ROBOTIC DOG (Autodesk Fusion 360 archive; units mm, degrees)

design "WAVEGO PRO BETA" references "SCS215", "支架"
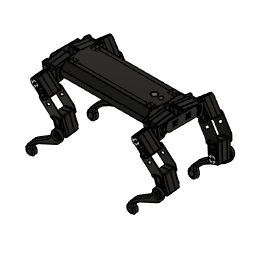
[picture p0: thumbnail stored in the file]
parameter "d7" = 1.5
parameter "d13" = 1.5
parameter "d21" = 2.5
parameter "d70" = 1.5
sketch "草图2" plane through (-2804.9918, -1775.266, 0) normal (0, 0, 1) x axis (1, 0, 0)
  line L1 (3425.3355, 1308.4769) -> (3426.7345, 1308.3163)
  line L2 (3447.7144, 1337.2156) -> (3447.3133, 1335.8658)
  line L3 (3434.7333, 1332.7657) -> (3435.8804, 1331.9489)
  line L4 (3453.3078, 1578.136) -> (3453.6616, 1576.7729)
  line L5 (3424.9361, 1311.1179) -> (3426.217, 1311.703)
  line L6 (3428.9646, 1326.8646) -> (3430.3219, 1326.4895)
  line L7 (3458.8158, 1577.0653) -> (3457.9772, 1575.934)
  line L8 (3439.6409, 1335.486) -> (3439.7256, 1334.0804)
  line L9 (3432.6458, 1331.0994) -> (3433.2062, 1329.8075)
  line L10 (3427.1623, 1303.1715) -> (3428.1658, 1304.1594)
  line L11 (3471.8291, 1318.4375) -> (3470.4301, 1318.5981)
  line L12 (3433.9754, 1294.6993) -> (3435.1504, 1295.4755)
  line L13 (3472.1305, 1310.1862) -> (3470.8708, 1310.8157)
  line L14 (3442.1724, 1336.3379) -> (3442.971, 1335.178)
  line L15 (3449.4501, 1289.6987) -> (3449.8513, 1291.0486)
  line L16 (3431.972, 1296.4657) -> (3432.5771, 1297.7373)
  line L17 (3470.0023, 1323.7429) -> (3468.9988, 1322.755)
  line L18 (3464.5187, 1295.815) -> (3463.9583, 1297.1069)
  line L19 (3425.034, 1316.7281) -> (3426.2937, 1316.0987)
  line L20 (3438.7851, 1291.8094) -> (3438.9188, 1293.2112)
  line L21 (3428.4408, 1300.8264) -> (3429.8103, 1301.1539)
  line L22 (3425.5621, 1319.3464) -> (3426.9658, 1319.4581)
  line L23 (3427.5729, 1324.5848) -> (3428.5414, 1323.5625)
  line L24 (3454.9922, 1290.5765) -> (3454.1935, 1291.7363)
  line L25 (3446.7799, 1289.764) -> (3446.4262, 1291.1271)
  line L26 (3471.6025, 1307.568) -> (3470.1987, 1307.4562)
  line L27 (3455.8926, 1336.0797) -> (3455.054, 1334.9484)
  line L28 (3450.3846, 1337.1503) -> (3450.7384, 1335.7873)
  line L29 (3458.3794, 1335.105) -> (3458.2457, 1333.7032)
  line L30 (3462.4313, 1294.1487) -> (3461.2841, 1294.9654)
  line L31 (3468.7238, 1326.088) -> (3467.3542, 1325.7605)
  line L32 (3463.1891, 1332.2151) -> (3462.0141, 1331.4389)
  line L33 (3441.2719, 1290.8347) -> (3442.1105, 1291.966)
  line L34 (3472.2284, 1315.7965) -> (3470.9475, 1315.2114)
  line L35 (3468.2, 1300.0497) -> (3466.8426, 1300.4249)
  line L36 (3457.5237, 1291.4283) -> (3457.4389, 1292.834)
  line L37 (3437.6565, 1573.7513) -> (3438.8036, 1572.9346)
  line L38 (3465.1926, 1330.4486) -> (3464.5875, 1329.1771)
  line L39 (3445.0956, 1577.3235) -> (3445.8942, 1576.1637)
  line L40 (3469.5916, 1302.3295) -> (3468.6232, 1303.3518)
  line L41 (3431.8878, 1567.8503) -> (3433.2451, 1567.4751)
  line L42 (3427.8593, 1552.1035) -> (3429.1402, 1552.6886)
  line L43 (3431.364, 1541.812) -> (3432.7335, 1542.1396)
  line L44 (3442.5641, 1576.4717) -> (3442.6488, 1575.066)
  line L45 (3428.4853, 1560.3321) -> (3429.889, 1560.4438)
  line L46 (3430.4961, 1565.5705) -> (3431.4646, 1564.5482)
  line L47 (3457.9153, 1531.5621) -> (3457.1167, 1532.722)
  line L48 (3428.2586, 1549.4625) -> (3429.6577, 1549.3019)
  line L49 (3450.6376, 1578.2013) -> (3450.2365, 1576.8514)
  line L50 (3465.3544, 1535.1343) -> (3464.2073, 1535.9511)
  line L51 (3452.3733, 1530.6844) -> (3452.7744, 1532.0342)
  line L52 (3436.8986, 1535.6849) -> (3438.0736, 1536.4612)
  line L53 (3441.7083, 1532.795) -> (3441.842, 1534.1968)
  line L54 (3444.1951, 1531.8203) -> (3445.0337, 1532.9516)
  line L55 (3434.8951, 1537.4514) -> (3435.5003, 1538.7229)
  line L56 (3460.4469, 1532.414) -> (3460.3621, 1533.8196)
  line L57 (3435.569, 1572.085) -> (3436.1294, 1570.7931)
  line L58 (3467.4419, 1536.8006) -> (3466.8815, 1538.0925)
  line L59 (3472.5148, 1543.3152) -> (3471.5464, 1544.3375)
  line L60 (3449.7031, 1530.7497) -> (3449.3494, 1532.1127)
  line L61 (3474.7523, 1559.4231) -> (3473.3533, 1559.5837)
  line L62 (3466.1123, 1573.2007) -> (3464.9373, 1572.4245)
  line L63 (3475.0537, 1551.1719) -> (3473.794, 1551.8013)
  line L64 (3430.0854, 1544.1571) -> (3431.089, 1545.145)
  line L65 (3475.1516, 1556.7821) -> (3473.8707, 1556.197)
  line L66 (3461.3026, 1576.0906) -> (3461.1689, 1574.6888)
  line L67 (3471.647, 1567.0736) -> (3470.2774, 1566.7461)
  line L68 (3472.9255, 1564.7285) -> (3471.9219, 1563.7406)
  line L69 (3427.9572, 1557.7138) -> (3429.2169, 1557.0843)
  line L70 (3468.1158, 1571.4343) -> (3467.5106, 1570.1627)
  line L71 (3471.1231, 1541.0354) -> (3469.7658, 1541.4105)
  line L72 (3474.5257, 1548.5536) -> (3473.1219, 1548.4419)
  line L73 (2864.3592, 1577.4683) -> (2882.3592, 1577.4683)
  line L74 (2855.3592, 1575.9683) -> (2855.3592, 1366.9683)
  line L75 (2882.3592, 1365.4683) -> (2864.3592, 1365.4683)
  line L76 (2882.3592, 1577.4683) -> (2894.3592, 1577.4683)
  line L77 (3684.4233, 1482.2767) -> (3273.5094, 1482.2767)
  line L78 (2868.1341, 1241.7898) -> (2902.3889, 1241.7898)
  line L79 (3450.2053, 1418.8111) -> (3444.2053, 1422.2752)
  line L80 (2863.9041, 1245.3984) -> (2867.0734, 1242.2291)
  line L81 (2923.389, 1259.793) -> (2922.229, 1264.1224)
  line L82 (2869.3498, 1247.3975) -> (2869.3498, 1249.0398)
  line L83 (3684.4233, 1603.763) -> (3684.4233, 1257.736)
  line L84 (3793.7104, 1574.3581) -> (3792.0673, 1572.7149)
  line L85 (2882.3592, 1365.4683) -> (2894.3592, 1365.4683)
  line L86 (3450.3053, 1432.8407) -> (3456.3053, 1429.3766)
  line L87 (2908.4677, 1244.64) -> (2908.645, 1244.5376)
  line L88 (2881.7917, 1250.6398) -> (2884.7917, 1250.6398)
  line L89 (2868.1341, 1271.4898) -> (2910.347, 1271.4898)
  line L90 (3456.3553, 1429.29) -> (3456.3553, 1422.3618)
  line L91 (2874.2917, 1263.4398) -> (2874.2917, 1249.8398)
  line L92 (3798.8404, 1565.9418) -> (3797.2732, 1567.509)
  line L93 (2880.2917, 1261.1398) -> (2880.2917, 1252.1398)
  line L94 (3450.3053, 1418.8111) -> (3456.3053, 1422.2752)
  line L95 (3450.2053, 1432.8407) -> (3444.2053, 1429.3766)
  line L96 (2908.4311, 1244.7766) -> (2909.2522, 1246.1988)
  line L97 (2886.2917, 1261.1398) -> (2886.2917, 1252.1398)
  line L98 (3811.2797, 1573.9877) -> (3824.0077, 1565.9598)
  line L99 (3684.4233, 1375.9852) -> (3273.5094, 1375.9852)
  line L100 (2894.3592, 1365.4683) -> (2912.3592, 1365.4683)
  line L101 (3444.1553, 1429.29) -> (3444.1553, 1422.3618)
  line L102 (2869.2498, 1265.9821) -> (2869.0451, 1265.9821)
  line L103 (2910.1433, 1243.6725) -> (2912.1438, 1242.5176)
  line L104 (3990.4322, 1603.763) -> (3729.1891, 1603.763)
  line L105 (2919.4856, 1259.8538) -> (2921.4861, 1258.6989)
  line L106 (2906.6801, 1239.3123) -> (2902.3889, 1241.7898)
  line L107 (2513.8475, 1418.2797) -> (2465.8475, 1418.2797)
  line L108 (2909.0692, 1246.8818) -> (2905.4822, 1248.9528)
  line L109 (2863.9041, 1267.8811) -> (2867.0734, 1271.0504)
  line L110 (2881.7917, 1262.6398) -> (2884.7917, 1262.6398)
  line L111 (2867.3149, 1247.2975) -> (2865.005, 1247.2975)
  line L112 (2912.1477, 1240.3225) -> (2907.8183, 1239.1624)
  line L113 (2905.3724, 1249.3626) -> (2912.1724, 1261.1405)
  line L114 (3729.1891, 1488.7955) -> (3990.4322, 1488.7955)
  line L115 (2869.3498, 1265.8821) -> (2869.3498, 1264.2398)
  line L116 (2869.2498, 1247.2975) -> (2869.0451, 1247.2975)
  line L117 (3729.1891, 1603.763) -> (3729.1891, 1488.7955)
  line L118 (2921.5301, 1265.0332) -> (2910.347, 1271.4898)
  line L119 (2867.3149, 1265.9821) -> (2865.005, 1265.9821)
  line L120 (2869.8498, 1249.5398) -> (2873.9917, 1249.5398)
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extrude "拉伸1" new body sketch "草图2" along normal blind 2
copy_paste "复制和粘贴1"
extrude "拉伸1" new body sketch "草图2" along normal blind 2
copy_paste "复制和粘贴2"
copy_paste "复制和粘贴3"
copy_paste "复制和粘贴4"
extrude "拉伸1" new body sketch "草图2" along normal blind 1.5
step "转换为钣金1"
step "折弯1" BendAngle 90 BendAngle 90 BendAngle 90 BendAngle 90 BendRadius 0.01
copy_paste "复制和粘贴5"
extrude "拉伸1" new body sketch "草图2" along normal blind 1.5
step "转换为钣金1"
step "折弯1" BendAngle 45 BendAngle 45 BendAngle 45 BendAngle 45 BendRadius 0.01
copy_paste "复制和粘贴6"
extrude "拉伸1" new body sketch "草图2" along normal blind 1.5
copy_paste "复制和粘贴7"
copy_paste "复制和粘贴8"
copy_paste "复制和粘贴9"
copy_paste "复制和粘贴10"
copy_paste "复制和粘贴11"
copy_paste "复制和粘贴12"
copy_paste "复制和粘贴13"
extrude "拉伸1" new body sketch "草图2" along normal blind 1.5
position "位置1"
position "位置2"
ground "地面"
joint "装配1" alignAngle 180 alignOffsetX 0 alignOffsetY 0 alignOffsetZ 0
joint "装配4" alignAngle 0 alignOffsetX 0 alignOffsetY 0 alignOffsetZ 0
joint "装配5" alignAngle 180 alignOffsetX 0 alignOffsetY 0 alignOffsetZ 0
move_face "MoveFace1"
move_face "MoveFace2"
move_face "MoveFace3"
move_face "MoveFace4"
move_face "MoveFace5"
joint "装配6" alignAngle 180 alignOffsetX 0 alignOffsetY 0 alignOffsetZ 0
component_insert "插入零部件1"
joint "装配7" alignAngle 0 alignOffsetX 0 alignOffsetY 0 alignOffsetZ 0
position "位置3"
component_insert "插入零部件2"
joint "装配8" alignAngle 180 alignOffsetX 0 alignOffsetY 0 alignOffsetZ 0
component_insert "插入零部件3"
component_insert "插入零部件4"
joint "装配9" alignAngle 180 alignOffsetX 0 alignOffsetY 0 alignOffsetZ 0
joint "装配10" alignAngle 0 alignOffsetX 0 alignOffsetY 0 alignOffsetZ 0
sketch "草图3" plane through (-2362.4388, -1816.6745, 0) normal (0, 0, 1) x axis (1, 0, 0)
  line L1 (2599.7507, 1404.8271) -> (2599.7507, 1406.4694)
  line L2 (2597.7158, 1423.4116) -> (2595.4059, 1423.4116)
  line L3 (2599.7507, 1423.3116) -> (2599.7507, 1421.6694)
  line L4 (2604.6926, 1420.8694) -> (2604.6926, 1407.2694)
  line L5 (2594.305, 1425.3107) -> (2597.4743, 1428.48)
  line L6 (2610.6926, 1428.9194) -> (2610.6926, 1399.2194)
  line L7 (2599.6507, 1423.4116) -> (2599.446, 1423.4116)
  line L8 (2598.535, 1399.2194) -> (2610.6926, 1399.2194)
  line L9 (2597.7158, 1404.7271) -> (2595.4059, 1404.7271)
  line L10 (2654.2345, 1404.7271) -> (2654.4393, 1404.7271)
  line L11 (2654.1345, 1404.8271) -> (2654.1345, 1406.4694)
  line L12 (2600.2507, 1421.1694) -> (2604.3926, 1421.1694)
  line L13 (2600.2507, 1406.9694) -> (2604.3926, 1406.9694)
  line L14 (2612.0926, 1428.9194) -> (2610.6926, 1428.9194)
  line L15 (2620.8122, 1460.1634) -> (2605.4335, 1460.1634)
  line L16 (2654.1345, 1423.3116) -> (2654.1345, 1421.6694)
  line L17 (2656.4335, 1676.1634) -> (2641.0549, 1676.1634)
  line L18 (2659.5803, 1402.828) -> (2656.411, 1399.6587)
  line L19 (2656.1694, 1404.7271) -> (2658.4793, 1404.7271)
  line L20 (2638.1926, 1402.8194) -> (2641.7926, 1399.2194)
  line L21 (2615.6926, 1402.8194) -> (2612.0926, 1399.2194)
  line L22 (2598.535, 1428.9194) -> (2610.6926, 1428.9194)
  line L23 (2599.6507, 1404.7271) -> (2599.446, 1404.7271)
  line L24 (2638.1926, 1402.8194) -> (2615.6926, 1402.8194)
  line L25 (2603.9335, 1674.6634) -> (2603.9335, 1461.6634)
  line L26 (2620.8122, 1676.1634) -> (2605.4335, 1676.1634)
  line L27 (2641.7926, 1428.9194) -> (2643.1926, 1428.9194)
  line L28 (2643.1926, 1428.9194) -> (2643.1926, 1399.2194)
  line L29 (2594.305, 1402.828) -> (2597.4743, 1399.6587)
  line L30 (2656.4335, 1460.1634) -> (2641.0549, 1460.1634)
  line L31 (2653.6345, 1421.1694) -> (2649.4926, 1421.1694)
  line L32 (2655.3503, 1399.2194) -> (2643.1926, 1399.2194)
  line L33 (2615.6926, 1425.3194) -> (2612.0926, 1428.9194)
  line L34 (2659.5803, 1425.3107) -> (2656.411, 1428.48)
  line L35 (2653.6345, 1406.9694) -> (2649.4926, 1406.9694)
  line L36 (2657.9335, 1461.6634) -> (2657.9335, 1674.6634)
  line L37 (2639.9942, 1459.7241) -> (2639.3729, 1459.1027)
  line L38 (2622.4942, 1459.1027) -> (2621.8729, 1459.7241)
  line L39 (2622.4942, 1677.2241) -> (2621.8729, 1676.6027)
  line L40 (2612.0926, 1399.2194) -> (2610.6926, 1399.2194)
  line L41 (2649.1926, 1420.8694) -> (2649.1926, 1407.2694)
  line L42 (2638.1926, 1425.3194) -> (2615.6926, 1425.3194)
  line L43 (2654.2345, 1423.4116) -> (2654.4393, 1423.4116)
  line L44 (2638.3122, 1677.6634) -> (2623.5549, 1677.6634)
  line L45 (2639.9942, 1676.6027) -> (2639.3729, 1677.2241)
  line L46 (2655.3503, 1428.9194) -> (2643.1926, 1428.9194)
  line L47 (2656.1694, 1423.4116) -> (2658.4793, 1423.4116)
  line L48 (2638.1926, 1425.3194) -> (2641.7926, 1428.9194)
  line L49 (2638.3122, 1458.6634) -> (2623.5549, 1458.6634)
  line L50 (2641.7926, 1399.2194) -> (2643.1926, 1399.2194)
  arc A1 centre (2598.5809, 1403.8194) radius 1 clockwise from (2599.3332, 1404.4782) to (2597.8287, 1404.4782)
  arc A2 centre (2595.0121, 1424.6036) radius 1 clockwise from (2594.2244, 1423.9875) to (2594.305, 1425.3107)
  arc A3 centre (2595.0121, 1403.5351) radius 1 clockwise from (2594.305, 1402.828) to (2594.2244, 1404.1512)
  arc A4 centre (2598.535, 1427.4194) radius 1.5 clockwise from (2597.4743, 1428.48) to (2598.535, 1428.9194)
  circle C1 centre (2602.3309, 1424.3194) radius 1
  arc A5 centre (2595.4059, 1403.2271) radius 1.5 clockwise from (2594.2244, 1404.1512) to (2595.4059, 1404.7271)
  arc A6 centre (2599.446, 1404.5771) radius 0.15 clockwise from (2599.3332, 1404.4782) to (2599.446, 1404.7271)
  arc A7 centre (2600.2507, 1406.4694) radius 0.5 clockwise from (2599.7507, 1406.4694) to (2600.2507, 1406.9694)
  arc A8 centre (2656.1694, 1404.5771) radius 0.15 clockwise from (2656.0566, 1404.4782) to (2656.1694, 1404.7271)
  arc A9 centre (2597.7158, 1404.5771) radius 0.15 clockwise from (2597.7158, 1404.7271) to (2597.8287, 1404.4782)
  arc A10 centre (2598.5809, 1424.3194) radius 1 clockwise from (2597.8287, 1423.6605) to (2599.3332, 1423.6605)
  arc A11 centre (2654.4393, 1404.5771) radius 0.15 clockwise from (2654.4393, 1404.7271) to (2654.5521, 1404.4782)
  arc A12 centre (2655.3043, 1403.8194) radius 1 clockwise from (2656.0566, 1404.4782) to (2654.5521, 1404.4782)
  circle C2 centre (2651.5543, 1403.8194) radius 1
  arc A13 centre (2653.6345, 1406.4694) radius 0.5 clockwise from (2653.6345, 1406.9694) to (2654.1345, 1406.4694)
  arc A14 centre (2598.535, 1400.7194) radius 1.5 clockwise from (2598.535, 1399.2194) to (2597.4743, 1399.6587)
  arc A15 centre (2599.6507, 1404.8271) radius 0.1 clockwise from (2599.7507, 1404.8271) to (2599.6507, 1404.7271)
  arc A16 centre (2597.7158, 1423.5616) radius 0.15 clockwise from (2597.8287, 1423.6605) to (2597.7158, 1423.4116)
  arc A17 centre (2631.8658, 1417.0593) radius 0.36 clockwise from (2631.5581, 1416.8724) to (2631.8707, 1417.4193)
  arc A18 centre (2604.3926, 1407.2694) radius 0.3 clockwise from (2604.6926, 1407.2694) to (2604.3926, 1406.9694)
  arc A19 centre (2605.4335, 1461.6634) radius 1.5 clockwise from (2605.4335, 1460.1634) to (2603.9335, 1461.6634)
  arc A20 centre (2620.8122, 1677.6634) radius 1.5 clockwise from (2621.8729, 1676.6027) to (2620.8122, 1676.1634)
  arc A21 centre (2629.9326, 1409.1462) radius 0.36 clockwise from (2629.7457, 1409.4539) to (2630.2925, 1409.1413)
  arc A22 centre (2649.4926, 1420.8694) radius 0.3 clockwise from (2649.1926, 1420.8694) to (2649.4926, 1421.1694)
  arc A23 centre (2626.9426, 1414.0694) radius 5.4 clockwise from (2629.7457, 1409.4539) to (2624.1396, 1409.4539)
  arc A24 centre (2600.2507, 1421.6694) radius 0.5 clockwise from (2600.2507, 1421.1694) to (2599.7507, 1421.6694)
  arc A25 centre (2655.3503, 1400.7194) radius 1.5 clockwise from (2656.411, 1399.6587) to (2655.3503, 1399.2194)
  arc A26 centre (2604.3926, 1420.8694) radius 0.3 clockwise from (2604.3926, 1421.1694) to (2604.6926, 1420.8694)
  arc A27 centre (2595.4059, 1424.9116) radius 1.5 clockwise from (2595.4059, 1423.4116) to (2594.2244, 1423.9875)
  circle C3 centre (2602.3309, 1403.8194) radius 1
  arc A28 centre (2654.4393, 1423.5616) radius 0.15 clockwise from (2654.5521, 1423.6605) to (2654.4393, 1423.4116)
  arc A29 centre (2629.9326, 1418.9926) radius 0.36 clockwise from (2630.2925, 1418.9974) to (2629.7457, 1418.6849)
  arc A30 centre (2641.0549, 1458.6634) radius 1.5 clockwise from (2639.9942, 1459.7241) to (2641.0549, 1460.1634)
  arc A31 centre (2654.2345, 1404.8271) radius 0.1 clockwise from (2654.2345, 1404.7271) to (2654.1345, 1404.8271)
  arc A32 centre (2622.0194, 1417.0593) radius 0.36 clockwise from (2622.0146, 1417.4193) to (2622.3271, 1416.8724)
  arc A33 centre (2656.1694, 1423.5616) radius 0.15 clockwise from (2656.1694, 1423.4116) to (2656.0566, 1423.6605)
  arc A34 centre (2626.9426, 1414.0694) radius 5.4 clockwise from (2631.5581, 1416.8724) to (2631.5581, 1411.2663)
  arc A35 centre (2655.3503, 1427.4194) radius 1.5 clockwise from (2655.3503, 1428.9194) to (2656.411, 1428.48)
  arc A36 centre (2599.446, 1423.5616) radius 0.15 clockwise from (2599.446, 1423.4116) to (2599.3332, 1423.6605)
  arc A37 centre (2599.6507, 1423.3116) radius 0.1 clockwise from (2599.6507, 1423.4116) to (2599.7507, 1423.3116)
  arc A38 centre (2653.6345, 1421.6694) radius 0.5 clockwise from (2654.1345, 1421.6694) to (2653.6345, 1421.1694)
  arc A39 centre (2622.0194, 1411.0794) radius 0.36 clockwise from (2622.3271, 1411.2663) to (2622.0146, 1410.7195)
  circle C4 centre (2653.4335, 1669.1634) radius 1.3
  arc A40 centre (2658.4793, 1424.9116) radius 1.5 clockwise from (2659.6608, 1423.9875) to (2658.4793, 1423.4116)
  arc A41 centre (2658.8732, 1424.6036) radius 1 clockwise from (2659.5803, 1425.3107) to (2659.6608, 1423.9875)
  arc A42 centre (2658.4793, 1403.2271) radius 1.5 clockwise from (2658.4793, 1404.7271) to (2659.6608, 1404.1512)
  circle C5 centre (2608.4335, 1477.1634) radius 1.3
  arc A43 centre (2656.4335, 1674.6634) radius 1.5 clockwise from (2656.4335, 1676.1634) to (2657.9335, 1674.6634)
  circle C6 centre (2651.5543, 1424.3194) radius 1
  circle C7 centre (2608.4335, 1659.1634) radius 1.3
  circle C8 centre (2630.9335, 1662.1634) radius 4
  arc A44 centre (2631.8658, 1411.0794) radius 0.36 clockwise from (2631.8707, 1410.7195) to (2631.5581, 1411.2663)
  arc A45 centre (2638.3122, 1676.1634) radius 1.5 clockwise from (2638.3122, 1677.6634) to (2639.3729, 1677.2241)
  arc A46 centre (2658.8732, 1403.5351) radius 1 clockwise from (2659.6608, 1404.1512) to (2659.5803, 1402.828)
  arc A47 centre (2623.9527, 1409.1462) radius 0.36 clockwise from (2623.5927, 1409.1413) to (2624.1396, 1409.4539)
  circle C9 centre (2653.4335, 1467.1634) radius 1.3
  circle C10 centre (2653.4335, 1659.1634) radius 1.3
  arc A48 centre (2605.4335, 1674.6634) radius 1.5 clockwise from (2603.9335, 1674.6634) to (2605.4335, 1676.1634)
  arc A49 centre (2626.9426, 1414.0694) radius 5.4 clockwise from (2622.3271, 1411.2663) to (2622.3271, 1416.8724)
  arc A50 centre (2623.5549, 1460.1634) radius 1.5 clockwise from (2623.5549, 1458.6634) to (2622.4942, 1459.1027)
  arc A51 centre (2626.9426, 1414.0694) radius 5.4 clockwise from (2624.1396, 1418.6849) to (2629.7457, 1418.6849)
  circle C11 centre (2608.4335, 1669.1634) radius 1.3
  circle C12 centre (2653.4335, 1477.1634) radius 1.3
  circle C13 centre (2630.9335, 1645.8634) radius 6
  arc A52 centre (2655.3043, 1424.3194) radius 1 clockwise from (2654.5521, 1423.6605) to (2656.0566, 1423.6605)
  arc A53 centre (2641.0549, 1677.6634) radius 1.5 clockwise from (2641.0549, 1676.1634) to (2639.9942, 1676.6027)
  arc A54 centre (2654.2345, 1423.3116) radius 0.1 clockwise from (2654.1345, 1423.3116) to (2654.2345, 1423.4116)
  arc A55 centre (2623.9527, 1418.9926) radius 0.36 clockwise from (2624.1396, 1418.6849) to (2623.5927, 1418.9974)
  arc A56 centre (2649.4926, 1407.2694) radius 0.3 clockwise from (2649.4926, 1406.9694) to (2649.1926, 1407.2694)
  arc A57 centre (2656.4335, 1461.6634) radius 1.5 clockwise from (2657.9335, 1461.6634) to (2656.4335, 1460.1634)
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place_component sketch "草图3"
extrude "拉伸1" new body sketch "草图3" along normal blind 1.5
extrude "拉伸1" new body sketch "草图3" along normal blind 1.5
step "转换为钣金1"
step "折弯1" BendAngle 90 BendAngle 90 BendRadius 0.01
copy_paste "复制和粘贴15"
copy_paste "复制和粘贴16"
copy_paste "复制和粘贴17"
joint "装配11" alignAngle 0 alignOffsetX 0 alignOffsetY 0 alignOffsetZ 0
joint "装配12" alignAngle 0 alignOffsetX 0 alignOffsetY 0 alignOffsetZ 0
joint "装配13" alignAngle 0 alignOffsetX 0 alignOffsetY 0 alignOffsetZ 0
joint "装配14" alignAngle 0 alignOffsetX 0 alignOffsetY 0 alignOffsetZ 0
position "位置4"
sketch "草图1" plane through (0, 0, 2) normal (0, 0, 1) x axis (-1, 0, 0)
  line L1 (291.1443, 356.9864) -> (339.1443, 356.9864)
  line L2 (339.1443, 326.9864) -> (291.1443, 326.9864)
  line L3 (279, 329.6538) -> (347.683, 329.6538)
  line L4 (345, 341.9864) -> (339.1443, 341.9864)
  line L5 (279, 354.3189) -> (347.683, 354.3189)
  arc A1 centre (331.1443, 341.9864) radius 5.4 clockwise from (333.9474, 337.3709) to (328.3412, 337.3709)
  arc A2 centre (328.1544, 337.0632) radius 0.36 clockwise from (327.7944, 337.0583) to (328.3412, 337.3709)
  arc A3 centre (326.1946, 337.0366) radius 1.6 clockwise from (327.7944, 337.0583) to (326.2162, 338.6365)
  arc A4 centre (326.2211, 338.9964) radius 0.36 clockwise from (326.5288, 339.1833) to (326.2162, 338.6365)
  arc A5 centre (331.1443, 341.9864) radius 5.4 clockwise from (326.5288, 339.1833) to (326.5288, 344.7894)
  arc A6 centre (326.2211, 344.9763) radius 0.36 clockwise from (326.2162, 345.3363) to (326.5288, 344.7894)
  arc A7 centre (326.1946, 346.9361) radius 1.6 clockwise from (326.2162, 345.3363) to (327.7944, 346.9144)
  arc A8 centre (328.1544, 346.9096) radius 0.36 clockwise from (328.3412, 346.6019) to (327.7944, 346.9144)
  arc A9 centre (331.1443, 341.9864) radius 5.4 clockwise from (328.3412, 346.6019) to (333.9474, 346.6019)
  arc A10 centre (334.1342, 346.9096) radius 0.36 clockwise from (334.4942, 346.9144) to (333.9474, 346.6019)
  arc A11 centre (336.0941, 346.9361) radius 1.6 clockwise from (334.4942, 346.9144) to (336.0724, 345.3363)
  arc A12 centre (336.0675, 344.9763) radius 0.36 clockwise from (335.7598, 344.7894) to (336.0724, 345.3363)
  arc A13 centre (331.1443, 341.9864) radius 5.4 clockwise from (335.7598, 344.7894) to (335.7598, 339.1833)
  arc A14 centre (336.0675, 338.9964) radius 0.36 clockwise from (336.0724, 338.6365) to (335.7598, 339.1833)
  arc A15 centre (336.0941, 337.0366) radius 1.6 clockwise from (336.0724, 338.6365) to (334.4942, 337.0583)
  arc A16 centre (334.1342, 337.0632) radius 0.36 clockwise from (333.9474, 337.3709) to (334.4942, 337.0583)
  arc A17 centre (304.0941, 346.9361) radius 1.6 clockwise from (302.4942, 346.9144) to (304.0724, 345.3363)
  arc A18 centre (304.0675, 344.9763) radius 0.36 clockwise from (303.7598, 344.7894) to (304.0724, 345.3363)
  arc A19 centre (299.1443, 341.9864) radius 5.4 clockwise from (303.7598, 344.7894) to (303.7598, 339.1833)
  arc A20 centre (304.0675, 338.9964) radius 0.36 clockwise from (304.0724, 338.6365) to (303.7598, 339.1833)
  arc A21 centre (304.0941, 337.0366) radius 1.6 clockwise from (304.0724, 338.6365) to (302.4942, 337.0583)
  arc A22 centre (302.1342, 337.0632) radius 0.36 clockwise from (301.9474, 337.3709) to (302.4942, 337.0583)
  arc A23 centre (299.1443, 341.9864) radius 5.4 clockwise from (301.9474, 337.3709) to (296.3412, 337.3709)
  arc A24 centre (296.1544, 337.0632) radius 0.36 clockwise from (295.7944, 337.0583) to (296.3412, 337.3709)
  arc A25 centre (294.1946, 337.0366) radius 1.6 clockwise from (295.7944, 337.0583) to (294.2162, 338.6365)
  arc A26 centre (294.2211, 338.9964) radius 0.36 clockwise from (294.5288, 339.1833) to (294.2162, 338.6365)
  arc A27 centre (299.1443, 341.9864) radius 5.4 clockwise from (294.5288, 339.1833) to (294.5288, 344.7894)
  arc A28 centre (294.2211, 344.9763) radius 0.36 clockwise from (294.2162, 345.3363) to (294.5288, 344.7894)
  arc A29 centre (294.1946, 346.9361) radius 1.6 clockwise from (294.2162, 345.3363) to (295.7944, 346.9144)
  arc A30 centre (296.1544, 346.9096) radius 0.36 clockwise from (296.3412, 346.6019) to (295.7944, 346.9144)
  arc A31 centre (299.1443, 341.9864) radius 5.4 clockwise from (296.3412, 346.6019) to (301.9474, 346.6019)
  arc A32 centre (302.1342, 346.9096) radius 0.36 clockwise from (302.4942, 346.9144) to (301.9474, 346.6019)
  arc A33 centre (291.1443, 341.9864) radius 15 clockwise from (291.1443, 326.9864) to (291.1443, 356.9864)
  arc A34 centre (339.1443, 341.9864) radius 15 clockwise from (339.1443, 356.9864) to (339.1443, 326.9864)
  point P66 (347.683, 329.6538)
  point P65 (339.1443, 341.9864)
  point P68 (339.1443, 341.9864)
  point P70 (347.683, 354.3189)
  point P67 (279, 329.6538)
  point P71 (279, 354.3189)
  coincident A34 P66
  horizontal L3
  coincident P65 P68
  horizontal L4
  symmetric P66 L4 P70
  symmetric P67 L4 P71
extrude "拉伸2" cut sketch "草图1" profile of L1 A33 L2 A34 L3 L5 along a picked direction blind -1.6
extrude "拉伸3" cut of existing geometry blind -0.4
component_insert "插入零部件5"
component_insert "插入零部件6"
joint "装配17" alignAngle 90 alignOffsetX 0 alignOffsetY 0 alignOffsetZ 0
joint "装配18" alignAngle 90 alignOffsetX 0 alignOffsetY 0 alignOffsetZ 0
joint "装配19" alignAngle 0 alignOffsetX 0 alignOffsetY 0 alignOffsetZ 0
component_insert "插入零部件7"
joint "装配20" alignAngle -90 alignOffsetX 0 alignOffsetY 0 alignOffsetZ 0
component_insert "插入零部件8"
joint "装配21" alignAngle -90 alignOffsetX 0 alignOffsetY 0 alignOffsetZ 0
joint "装配22" alignAngle 0 alignOffsetX 0 alignOffsetY 0 alignOffsetZ 0
joint "装配23" alignAngle 0 alignOffsetX 0 alignOffsetY 0 alignOffsetZ 0
joint "装配24" alignAngle 0 alignOffsetX 0 alignOffsetY 0 alignOffsetZ 0
joint "装配25" alignAngle 0 alignOffsetX 0 alignOffsetY 0 alignOffsetZ 0
joint "装配26" alignAngle 0 alignOffsetX 0 alignOffsetY 0 alignOffsetZ 0
joint "装配27" alignAngle 0 alignOffsetX 0 alignOffsetY 0 alignOffsetZ 0
joint "装配28" alignAngle 0 alignOffsetX 0 alignOffsetY 0 alignOffsetZ 0
joint "装配29" alignAngle 0 alignOffsetX 0 alignOffsetY 0 alignOffsetZ 0
component_insert "插入零部件9"
joint "装配30" alignAngle 150 alignOffsetX 0 alignOffsetY 0 alignOffsetZ 0
position "位置5"
component_insert "插入零部件10"
joint "装配31" alignAngle 150 alignOffsetX 0 alignOffsetY 0 alignOffsetZ 0
component_insert "插入零部件11"
joint "装配32" alignAngle 210 alignOffsetX 0 alignOffsetY 0 alignOffsetZ 0
component_insert "插入零部件12"
joint "装配33" alignAngle 210 alignOffsetX 0 alignOffsetY 0 alignOffsetZ 0
joint "装配34" alignAngle 90 alignOffsetX 0 alignOffsetY 0 alignOffsetZ 0
joint "装配35" alignAngle 90 alignOffsetX 0 alignOffsetY 0 alignOffsetZ 0
joint "装配36" alignAngle -90 alignOffsetX 0 alignOffsetY 0 alignOffsetZ 0
joint "装配37" alignAngle -90 alignOffsetX 0 alignOffsetY 0 alignOffsetZ 0
component_insert "插入零部件13"
joint "装配38" alignAngle 0 alignOffsetX 0 alignOffsetY 0 alignOffsetZ 0
position "位置6" RotateAboutZ -45
component_insert "插入零部件14"
joint "装配39" alignAngle 90 alignOffsetX 0 alignOffsetY 0 alignOffsetZ 0
component_insert "插入零部件15"
joint "装配40" alignAngle 90 alignOffsetX 0 alignOffsetY 0 alignOffsetZ 0
component_insert "插入零部件16"
joint "装配41" alignAngle 90 alignOffsetX 0 alignOffsetY 0 alignOffsetZ 0
position "位置7" RotateAboutZ -8 RotateAboutZ 8 RotateAboutZ 20 RotateAboutZ 8 RotateAboutZ -8 RotateAboutZ -70 RotateAboutZ -40 RotateAboutZ -70 RotateAboutZ 40 RotateAboutZ -70 RotateAboutZ 40 RotateAboutZ -40
sketch "草图1" plane through (0, 0, 38.52) normal (0, 0, 1) x axis (-1, 0, 0)
  line L1 (88.0607, -8.4393) -> (87.4393, -9.0607)
  line L2 (88.5, 7.3787) -> (88.5, -7.3787)
  line L3 (87.4393, 9.0607) -> (88.0607, 8.4393)
  line L4 (87, 25.5) -> (87, 10.1213)
  line L5 (-127.5, 27) -> (85.5, 27)
  line L6 (-129, 10.1213) -> (-129, 25.5)
  line L7 (-130.0607, 8.4393) -> (-129.4393, 9.0607)
  line L8 (-130.5, -7.3787) -> (-130.5, 7.3787)
  line L9 (-129.4393, -9.0607) -> (-130.0607, -8.4393)
  line L10 (-129, -25.5) -> (-129, -10.1213)
  line L11 (85.5, -27) -> (-127.5, -27)
  line L12 (87, -10.1213) -> (87, -25.5)
  circle C1 centre (-122, 22.5) radius 1.3
  circle C2 centre (80, 22.5) radius 1.3
  circle C3 centre (80, -22.5) radius 1.3
  circle C4 centre (-115, 0) radius 4
  circle C5 centre (-122, -22.5) radius 1.3
  circle C6 centre (-112, -22.5) radius 1.3
  circle C7 centre (-112, 22.5) radius 1.3
  circle C8 centre (70, 22.5) radius 1.3
  circle C9 centre (70, -22.5) radius 1.3
  circle C10 centre (-98.7, 0) radius 6
  arc A1 centre (87, -7.3787) radius 1.5 clockwise from (88.5, -7.3787) to (88.0607, -8.4393)
  arc A2 centre (87, 7.3787) radius 1.5 clockwise from (88.0607, 8.4393) to (88.5, 7.3787)
  arc A3 centre (88.5, 10.1213) radius 1.5 clockwise from (87.4393, 9.0607) to (87, 10.1213)
  arc A4 centre (85.5, 25.5) radius 1.5 clockwise from (85.5, 27) to (87, 25.5)
  arc A5 centre (-127.5, 25.5) radius 1.5 clockwise from (-129, 25.5) to (-127.5, 27)
  arc A6 centre (-130.5, 10.1213) radius 1.5 clockwise from (-129, 10.1213) to (-129.4393, 9.0607)
  arc A7 centre (-129, 7.3787) radius 1.5 clockwise from (-130.5, 7.3787) to (-130.0607, 8.4393)
  arc A8 centre (-129, -7.3787) radius 1.5 clockwise from (-130.0607, -8.4393) to (-130.5, -7.3787)
  arc A9 centre (-130.5, -10.1213) radius 1.5 clockwise from (-129.4393, -9.0607) to (-129, -10.1213)
  arc A10 centre (-127.5, -25.5) radius 1.5 clockwise from (-127.5, -27) to (-129, -25.5)
  arc A11 centre (85.5, -25.5) radius 1.5 clockwise from (87, -25.5) to (85.5, -27)
  arc A12 centre (88.5, -10.1213) radius 1.5 clockwise from (87, -10.1213) to (87.4393, -9.0607)
  circle C11 centre (-98.7, 0) radius 7.5
  circle C12 centre (-115, 0) radius 5
  concentric C10 C11
  concentric C4 C12
  dimension "d215" diameter C11 = 15
  dimension "d216" diameter C12 = 10
extrude "拉伸1" new body sketch "草图1" profile of C4 C10 C11 C12 along normal blind 1
joint "装配42" alignAngle 0 alignOffsetX 0 alignOffsetY 0 alignOffsetZ -38.5
joint "装配43" alignAngle 180 alignOffsetX 0 alignOffsetY 0 alignOffsetZ -38.7
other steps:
create_component "创建零部件1"
create_component "创建零部件2"
create_component "创建零部件3"
create_component "创建零部件4"
create_component "创建零部件5"
create_component "创建零部件6"
joint_origin "联接原点1"
joint_origin "联接原点1"
joint_origin "联接原点1"
joint_origin "联接原点4"
joint_origin "联接原点5"
joint_origin "联接原点2"
joint_origin "联接原点3"
joint_origin "联接原点6"
joint_origin "联接原点7"
joint_origin "联接原点8"
joint_origin "联接原点9"
joint_origin "联接原点10"
create_component "创建零部件7" sketch "草图3"
create_component "创建零部件8"
joint_origin "联接原点1"
joint_origin "联接原点2"
joint_origin "联接原点3"
joint_origin "联接原点4"
joint_origin "联接原点5"
joint_origin "联接原点6"
joint_origin "联接原点1" sketch "草图3"
joint_origin "联接原点11"
joint_origin "联接原点7"
joint_origin "联接原点8"
joint_origin "联接原点1"
joint_origin "联接原点2"
joint_origin "联接原点3"
joint_origin "联接原点4"
joint_origin "联接原点5"
joint_origin "联接原点6"
joint_origin "联接原点7"
joint_origin "联接原点8"
joint_origin "联接原点9"
joint_origin "联接原点10"
joint_origin "联接原点11"
joint_origin "联接原点12"
joint_origin "联接原点1"
joint_origin "联接原点2"
joint_origin "联接原点3"
joint_origin "联接原点4"
joint_origin "联接原点5"
joint_origin "联接原点6"
joint_origin "联接原点7"
joint_origin "联接原点8"
create_component "创建零部件9"
joint_origin "联接原点3"
joint_origin "联接原点12"
joint_origin "联接原点4"
joint_origin "联接原点13"

design "金属舵盘（驱动）"
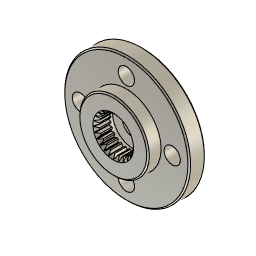
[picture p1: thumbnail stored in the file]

design "支架"
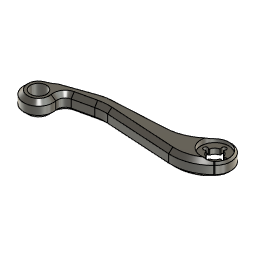
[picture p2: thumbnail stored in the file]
sketch "草图1" plane through (-2623.7756, -1634.3966, 0) normal (0, 0, 1) x axis (1, 0, 0)
  line L1 (2674.0131, 1638.7179) -> (2675.9637, 1640.6686)
  line L2 (2605.2201, 1625.4723) -> (2583.3542, 1617.7288)
  line L3 (2619.1732, 1616.9491) -> (2667.9411, 1613.9702)
  line L4 (2653.1341, 1629.3931) -> (2614.1539, 1627.2601)
  line L5 (2595.759, 1612.964) -> (2610.1659, 1616.221)
  line L6 (2692.5195, 1623.2833) -> (2692.9343, 1623.698)
  arc A1 centre (2678.8536, 1633.5503) radius 0.36 clockwise from (2679.2033, 1633.4649) to (2678.5956, 1633.2992)
  arc A2 centre (2685.8161, 1637.7787) radius 0.36 clockwise from (2685.7306, 1637.429) to (2685.565, 1638.0367)
  arc A3 centre (2683.082, 1637.7787) radius 0.36 clockwise from (2683.3331, 1638.0367) to (2683.1674, 1637.429)
  arc A4 centre (2685.8161, 1626.5879) radius 0.36 clockwise from (2685.565, 1626.3299) to (2685.7306, 1626.9376)
  arc A5 centre (2684.449, 1632.1833) radius 12 clockwise from (2675.9637, 1640.6686) to (2692.9343, 1623.698)
  arc A6 centre (2684.449, 1632.1833) radius 5.4 clockwise from (2679.2033, 1633.4649) to (2683.1674, 1637.429)
  arc A7 centre (2690.0445, 1633.5503) radius 0.36 clockwise from (2690.3024, 1633.2993) to (2689.6947, 1633.4649)
  arc A8 centre (2678.8536, 1630.8163) radius 0.36 clockwise from (2678.5956, 1631.0674) to (2679.2033, 1630.9017)
  arc A9 centre (2684.449, 1632.1833) radius 5.4 clockwise from (2685.7306, 1637.429) to (2689.6947, 1633.4649)
  arc A10 centre (2690.0445, 1630.8163) radius 0.36 clockwise from (2689.6947, 1630.9017) to (2690.3024, 1631.0674)
  arc A11 centre (2651.3857, 1661.3453) radius 32 clockwise from (2674.0131, 1638.7179) to (2653.1341, 1629.3931)
  arc A12 centre (2669.8921, 1645.9107) radius 32 clockwise from (2692.5195, 1623.2833) to (2667.9411, 1613.9702)
  circle C1 centre (2580.4235, 1603.722) radius 6
  arc A13 centre (2684.449, 1632.1833) radius 5.4 clockwise from (2683.1674, 1626.9376) to (2679.2033, 1630.9017)
  arc A14 centre (2683.082, 1626.5879) radius 0.36 clockwise from (2683.1674, 1626.9376) to (2683.3331, 1626.3299)
  arc A15 centre (2684.449, 1632.1833) radius 5.4 clockwise from (2689.6947, 1630.9017) to (2685.7306, 1626.9376)
  arc A16 centre (2585.3572, 1612.073) radius 6 clockwise from (2581.6043, 1616.7545) to (2583.3542, 1617.7288)
  arc A17 centre (2617.2222, 1585.0087) radius 32 clockwise from (2610.1659, 1616.221) to (2619.1732, 1616.9491)
  arc A18 centre (2580.4235, 1603.722) radius 11 clockwise from (2591.2026, 1605.9153) to (2576.8274, 1614.1176)
  arc A19 centre (2571.5968, 1629.2384) radius 16 clockwise from (2581.6043, 1616.7545) to (2576.8274, 1614.1176)
  arc A20 centre (2615.9024, 1595.3079) radius 32 clockwise from (2605.2201, 1625.4723) to (2614.1539, 1627.2601)
  arc A21 centre (2597.0821, 1607.1117) radius 6 clockwise from (2591.2026, 1605.9153) to (2595.759, 1612.964)
  arc A22 centre (2684.449, 1639.1833) radius 1.6 clockwise from (2683.3331, 1638.0367) to (2685.565, 1638.0367)
  arc A23 centre (2691.449, 1632.1833) radius 1.6 clockwise from (2690.3024, 1633.2993) to (2690.3024, 1631.0674)
  arc A24 centre (2684.449, 1625.1833) radius 1.6 clockwise from (2685.565, 1626.3299) to (2683.3331, 1626.3299)
  arc A25 centre (2677.449, 1632.1833) radius 1.6 clockwise from (2678.5956, 1631.0674) to (2678.5956, 1633.2992)
extrude "拉伸1" new body sketch "草图1" along normal blind 12
chamfer "倒角" distance 3
sketch "草图2" plane through (0, 0, 12) normal (0, 0, 1) x axis (-1, 0, 0)
  line L1 (-44.3484, 17.432) -> (4.4195, 14.453)
  line L2 (-67.0374, 8.5772) -> (-66.6227, 8.992)
  line L3 (-52.3588, -2.2) -> (-54.3095, -4.1507)
  line L4 (9.4577, 10.132) -> (-29.5225, 7.999)
  line L5 (39.4199, 19.4957) -> (17.554, 11.7522)
  line L6 (14.2712, 15.2494) -> (28.678, 18.5064)
  arc A1 centre (-60.6735, 2.2133) radius 5.4 clockwise from (-55.4278, 0.9317) to (-59.3919, -3.0324)
  arc A2 centre (-59.3064, -3.3821) radius 0.36 clockwise from (-59.5575, -3.6401) to (-59.3919, -3.0324)
  arc A3 centre (-60.6735, -4.7867) radius 1.6 clockwise from (-59.5575, -3.6401) to (-61.7894, -3.6401)
  arc A4 centre (-62.0405, -3.3821) radius 0.36 clockwise from (-61.9551, -3.0324) to (-61.7894, -3.6401)
  arc A5 centre (-60.6735, 2.2133) radius 5.4 clockwise from (-61.9551, -3.0324) to (-65.9192, 0.9317)
  arc A6 centre (-66.2689, 0.8462) radius 0.36 clockwise from (-66.5269, 1.0973) to (-65.9192, 0.9317)
  arc A7 centre (-67.6735, 2.2133) radius 1.6 clockwise from (-66.5269, 1.0973) to (-66.5269, 3.3292)
  arc A8 centre (-66.2689, 3.5803) radius 0.36 clockwise from (-65.9192, 3.4949) to (-66.5269, 3.3292)
  arc A9 centre (-60.6735, 2.2133) radius 5.4 clockwise from (-65.9192, 3.4949) to (-61.9551, 7.459)
  arc A10 centre (-62.0405, 7.8087) radius 0.36 clockwise from (-61.7894, 8.0667) to (-61.9551, 7.459)
  arc A11 centre (-60.6735, 9.2133) radius 1.6 clockwise from (-61.7894, 8.0667) to (-59.5575, 8.0667)
  arc A12 centre (-59.3064, 7.8087) radius 0.36 clockwise from (-59.3919, 7.459) to (-59.5575, 8.0667)
  arc A13 centre (-60.6735, 2.2133) radius 5.4 clockwise from (-59.3919, 7.459) to (-55.4278, 3.4949)
  arc A14 centre (-55.078, 3.5803) radius 0.36 clockwise from (-54.8201, 3.3292) to (-55.4278, 3.4949)
  arc A15 centre (-53.6735, 2.2133) radius 1.6 clockwise from (-54.8201, 3.3292) to (-54.8201, 1.0973)
  arc A16 centre (-55.078, 0.8463) radius 0.36 clockwise from (-55.4278, 0.9317) to (-54.8201, 1.0973)
  circle C1 centre (43.3521, 30.6746) radius 6
  arc A17 centre (-46.1166, -11.5141) radius 29 clockwise from (-66.6227, 8.992) to (-44.3484, 17.432)
  arc A18 centre (-60.6735, 2.2133) radius 9 clockwise from (-54.3095, -4.1507) to (-67.0374, 8.5772)
  arc A19 centre (-27.6101, -26.9487) radius 35 clockwise from (-52.3588, -2.2) to (-29.5225, 7.999)
  arc A20 centre (7.8732, 39.0887) radius 29 clockwise from (17.554, 11.7522) to (9.4577, 10.132)
  arc A21 centre (38.4184, 22.3236) radius 3 clockwise from (40.2948, 19.9829) to (39.4199, 19.4957)
  arc A22 centre (52.1787, 5.1582) radius 19 clockwise from (40.2948, 19.9829) to (45.9674, 23.1142)
  arc A23 centre (43.3521, 30.6746) radius 8 clockwise from (35.5127, 29.0795) to (45.9674, 23.1142)
  arc A24 centre (26.6935, 27.2849) radius 9 clockwise from (35.5127, 29.0795) to (28.678, 18.5064)
  arc A25 centre (6.5534, 49.3879) radius 35 clockwise from (14.2712, 15.2494) to (4.4195, 14.453)
  circle C2 centre (-53.6735, 2.2133) radius 2.75
  circle C3 centre (-53.6735, 2.2133) radius 2.75
  circle C4 centre (-60.6735, 9.2133) radius 2.75
  circle C5 centre (-67.6735, 2.2133) radius 2.75
  circle C6 centre (-60.6735, -4.7867) radius 2.75
  concentric A15 C2
  concentric A11 C4
  concentric A7 C5
  concentric A3 C6
  dimension "d4" diameter C2 = 5.5
  dimension "d5" diameter C3 = 5.5
  dimension "d6" diameter C4 = 5.5
  dimension "d7" diameter C5 = 5.5
  dimension "d8" diameter C6 = 5.5
sketch "草图3" plane through (0, 0, 12) normal (0, 0, 1) x axis (-1, 0, 0)
  line L1 (-44.3484, 17.432) -> (4.4195, 14.453)
  line L2 (-67.0374, 8.5772) -> (-66.6227, 8.992)
  line L3 (-52.3588, -2.2) -> (-54.3095, -4.1507)
  line L4 (9.4577, 10.132) -> (-29.5225, 7.999)
  line L5 (39.4199, 19.4957) -> (17.554, 11.7522)
  line L6 (14.2712, 15.2494) -> (28.678, 18.5064)
  arc A1 centre (-60.6735, 2.2133) radius 5.4 clockwise from (-55.4278, 0.9317) to (-59.3919, -3.0324)
  arc A2 centre (-59.3064, -3.3821) radius 0.36 clockwise from (-59.5575, -3.6401) to (-59.3919, -3.0324)
  arc A3 centre (-60.6735, -4.7867) radius 1.6 clockwise from (-59.5575, -3.6401) to (-61.7894, -3.6401)
  arc A4 centre (-62.0405, -3.3821) radius 0.36 clockwise from (-61.9551, -3.0324) to (-61.7894, -3.6401)
  arc A5 centre (-60.6735, 2.2133) radius 5.4 clockwise from (-61.9551, -3.0324) to (-65.9192, 0.9317)
  arc A6 centre (-66.2689, 0.8462) radius 0.36 clockwise from (-66.5269, 1.0973) to (-65.9192, 0.9317)
  arc A7 centre (-67.6735, 2.2133) radius 1.6 clockwise from (-66.5269, 1.0973) to (-66.5269, 3.3292)
  arc A8 centre (-66.2689, 3.5803) radius 0.36 clockwise from (-65.9192, 3.4949) to (-66.5269, 3.3292)
  arc A9 centre (-60.6735, 2.2133) radius 5.4 clockwise from (-65.9192, 3.4949) to (-61.9551, 7.459)
  arc A10 centre (-62.0405, 7.8087) radius 0.36 clockwise from (-61.7894, 8.0667) to (-61.9551, 7.459)
  arc A11 centre (-60.6735, 9.2133) radius 1.6 clockwise from (-61.7894, 8.0667) to (-59.5575, 8.0667)
  arc A12 centre (-59.3064, 7.8087) radius 0.36 clockwise from (-59.3919, 7.459) to (-59.5575, 8.0667)
  arc A13 centre (-60.6735, 2.2133) radius 5.4 clockwise from (-59.3919, 7.459) to (-55.4278, 3.4949)
  arc A14 centre (-55.078, 3.5803) radius 0.36 clockwise from (-54.8201, 3.3292) to (-55.4278, 3.4949)
  arc A15 centre (-53.6735, 2.2133) radius 1.6 clockwise from (-54.8201, 3.3292) to (-54.8201, 1.0973)
  arc A16 centre (-55.078, 0.8463) radius 0.36 clockwise from (-55.4278, 0.9317) to (-54.8201, 1.0973)
  circle C1 centre (43.3521, 30.6746) radius 6
  arc A17 centre (-46.1166, -11.5141) radius 29 clockwise from (-66.6227, 8.992) to (-44.3484, 17.432)
  arc A18 centre (-60.6735, 2.2133) radius 9 clockwise from (-54.3095, -4.1507) to (-67.0374, 8.5772)
  arc A19 centre (-27.6101, -26.9487) radius 35 clockwise from (-52.3588, -2.2) to (-29.5225, 7.999)
  arc A20 centre (7.8732, 39.0887) radius 29 clockwise from (17.554, 11.7522) to (9.4577, 10.132)
  arc A21 centre (38.4184, 22.3236) radius 3 clockwise from (40.2948, 19.9829) to (39.4199, 19.4957)
  arc A22 centre (52.1787, 5.1582) radius 19 clockwise from (40.2948, 19.9829) to (45.9674, 23.1142)
  arc A23 centre (43.3521, 30.6746) radius 8 clockwise from (35.5127, 29.0795) to (45.9674, 23.1142)
  arc A24 centre (26.6935, 27.2849) radius 9 clockwise from (35.5127, 29.0795) to (28.678, 18.5064)
  arc A25 centre (6.5534, 49.3879) radius 35 clockwise from (14.2712, 15.2494) to (4.4195, 14.453)
  circle C2 centre (-60.6735, 2.2133) radius 10.5
  concentric A1 C2
  dimension "d11" diameter C2 = 21
extrude "拉伸3" cut sketch "草图3" profile of A1 A2 A3 A4 A5 A6 A7 A8 A9 A10 A11 A12 A13 A14 A15 A16 A17 L2 A18 L3 A19 C2 against normal blind 4
sketch "草图4" plane through (0, 0, 0) normal (0, 0, -1) x axis (1, 0, 0)
  line L1 (-4.4195, 14.453) -> (44.3484, 17.432)
  line L2 (-28.678, 18.5064) -> (-14.2712, 15.2494)
  line L3 (-17.554, 11.7522) -> (-39.4199, 19.4957)
  line L4 (29.5225, 7.999) -> (-9.4577, 10.132)
  line L5 (54.3095, -4.1507) -> (52.3588, -2.2)
  line L6 (66.6227, 8.992) -> (67.0374, 8.5772)
  arc A1 centre (60.6735, 2.2133) radius 5.4 clockwise from (59.3919, -3.0324) to (55.4278, 0.9317)
  arc A2 centre (55.078, 0.8463) radius 0.36 clockwise from (54.8201, 1.0973) to (55.4278, 0.9317)
  arc A3 centre (53.6735, 2.2133) radius 1.6 clockwise from (54.8201, 1.0973) to (54.8201, 3.3292)
  arc A4 centre (55.078, 3.5803) radius 0.36 clockwise from (55.4278, 3.4949) to (54.8201, 3.3292)
  arc A5 centre (60.6735, 2.2133) radius 5.4 clockwise from (55.4278, 3.4949) to (59.3919, 7.459)
  arc A6 centre (59.3064, 7.8087) radius 0.36 clockwise from (59.5575, 8.0667) to (59.3919, 7.459)
  arc A7 centre (60.6735, 9.2133) radius 1.6 clockwise from (59.5575, 8.0667) to (61.7894, 8.0667)
  arc A8 centre (62.0405, 7.8087) radius 0.36 clockwise from (61.9551, 7.459) to (61.7894, 8.0667)
  arc A9 centre (60.6735, 2.2133) radius 5.4 clockwise from (61.9551, 7.459) to (65.9192, 3.4949)
  arc A10 centre (66.2689, 3.5803) radius 0.36 clockwise from (66.5269, 3.3292) to (65.9192, 3.4949)
  arc A11 centre (67.6735, 2.2133) radius 1.6 clockwise from (66.5269, 3.3292) to (66.5269, 1.0973)
  arc A12 centre (66.2689, 0.8462) radius 0.36 clockwise from (65.9192, 0.9317) to (66.5269, 1.0973)
  arc A13 centre (60.6735, 2.2133) radius 5.4 clockwise from (65.9192, 0.9317) to (61.9551, -3.0324)
  arc A14 centre (62.0405, -3.3821) radius 0.36 clockwise from (61.7894, -3.6401) to (61.9551, -3.0324)
  arc A15 centre (60.6735, -4.7867) radius 1.6 clockwise from (61.7894, -3.6401) to (59.5575, -3.6401)
  arc A16 centre (59.3064, -3.3821) radius 0.36 clockwise from (59.3919, -3.0324) to (59.5575, -3.6401)
  circle C1 centre (-43.3521, 30.6746) radius 6
  arc A17 centre (-6.5534, 49.3879) radius 35 clockwise from (-4.4195, 14.453) to (-14.2712, 15.2494)
  arc A18 centre (-26.6935, 27.2849) radius 9 clockwise from (-28.678, 18.5064) to (-35.5127, 29.0795)
  arc A19 centre (-43.3521, 30.6746) radius 8 clockwise from (-45.9674, 23.1142) to (-35.5127, 29.0795)
  arc A20 centre (-52.1787, 5.1582) radius 19 clockwise from (-45.9674, 23.1142) to (-40.2948, 19.9829)
  arc A21 centre (-38.4184, 22.3236) radius 3 clockwise from (-39.4199, 19.4957) to (-40.2948, 19.9829)
  arc A22 centre (-7.8732, 39.0887) radius 29 clockwise from (-9.4577, 10.132) to (-17.554, 11.7522)
  arc A23 centre (27.6101, -26.9487) radius 35 clockwise from (29.5225, 7.999) to (52.3588, -2.2)
  arc A24 centre (60.6735, 2.2133) radius 9 clockwise from (67.0374, 8.5772) to (54.3095, -4.1507)
  arc A25 centre (46.1166, -11.5141) radius 29 clockwise from (44.3484, 17.432) to (66.6227, 8.992)
  circle C2 centre (60.6735, 2.2133) radius 10.5
  concentric A1 C2
  dimension "d14" diameter C2 = 21
extrude "拉伸4" cut sketch "草图4" profile of A1 A2 A3 A4 A5 A6 A7 A8 A9 A10 A11 A12 A13 A14 A15 A16 A23 L5 A24 L6 A25 C2 against normal blind 4

design "金属舵盘（从动）"
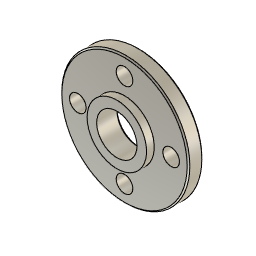
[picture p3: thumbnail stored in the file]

design "SCS215" references "金属舵盘（驱动）", "金属舵盘（从动）"
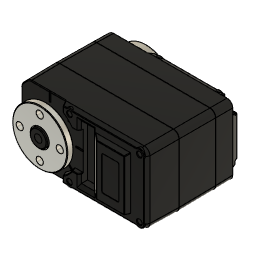
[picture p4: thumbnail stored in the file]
